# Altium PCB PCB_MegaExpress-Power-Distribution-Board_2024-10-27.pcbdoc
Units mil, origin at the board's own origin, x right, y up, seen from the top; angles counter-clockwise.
Board outline 2590 x 2205 mil, 2 copper layers (Top Layer, Bottom Layer); 6 components, 4 nets, 16 pads, 0 vias.
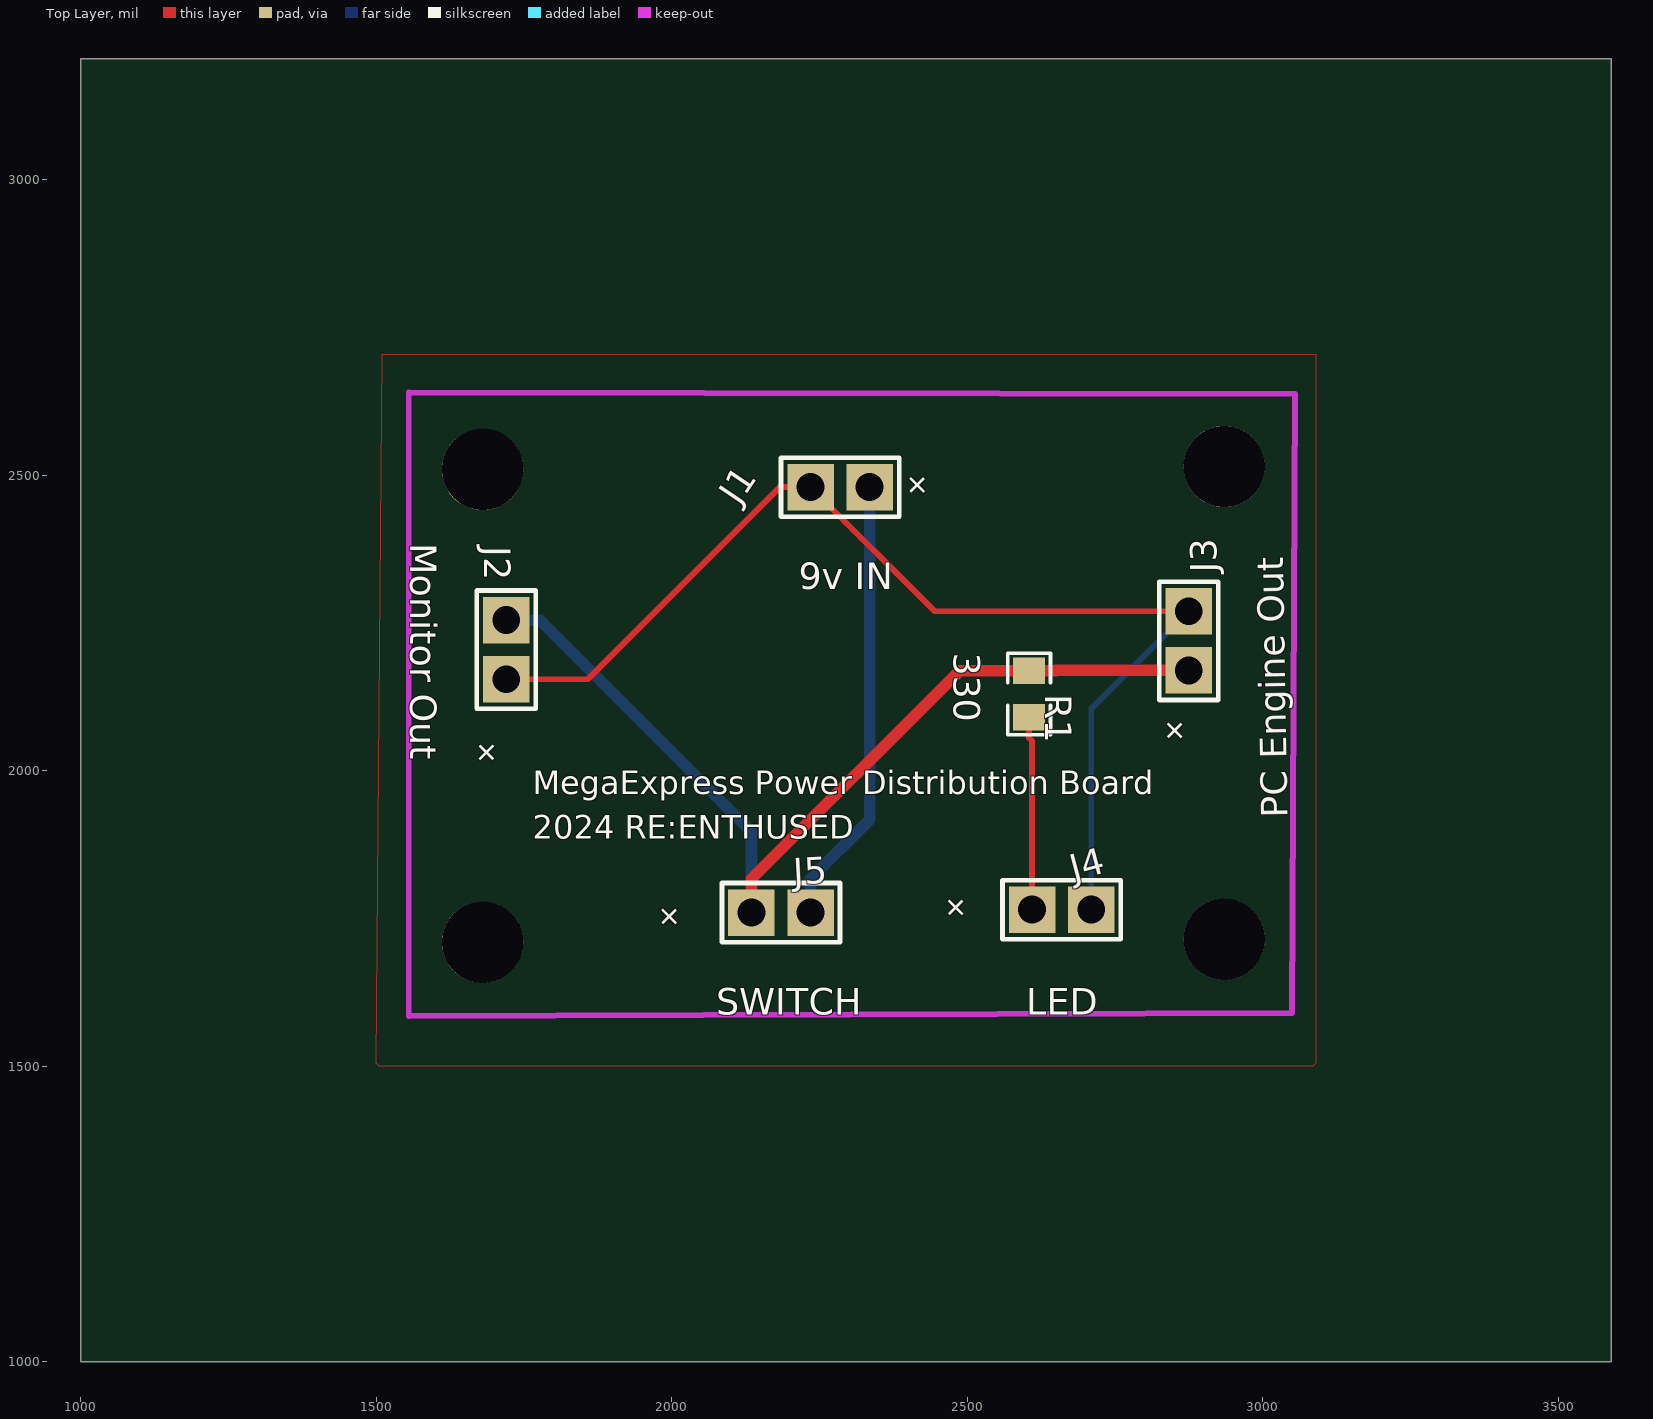
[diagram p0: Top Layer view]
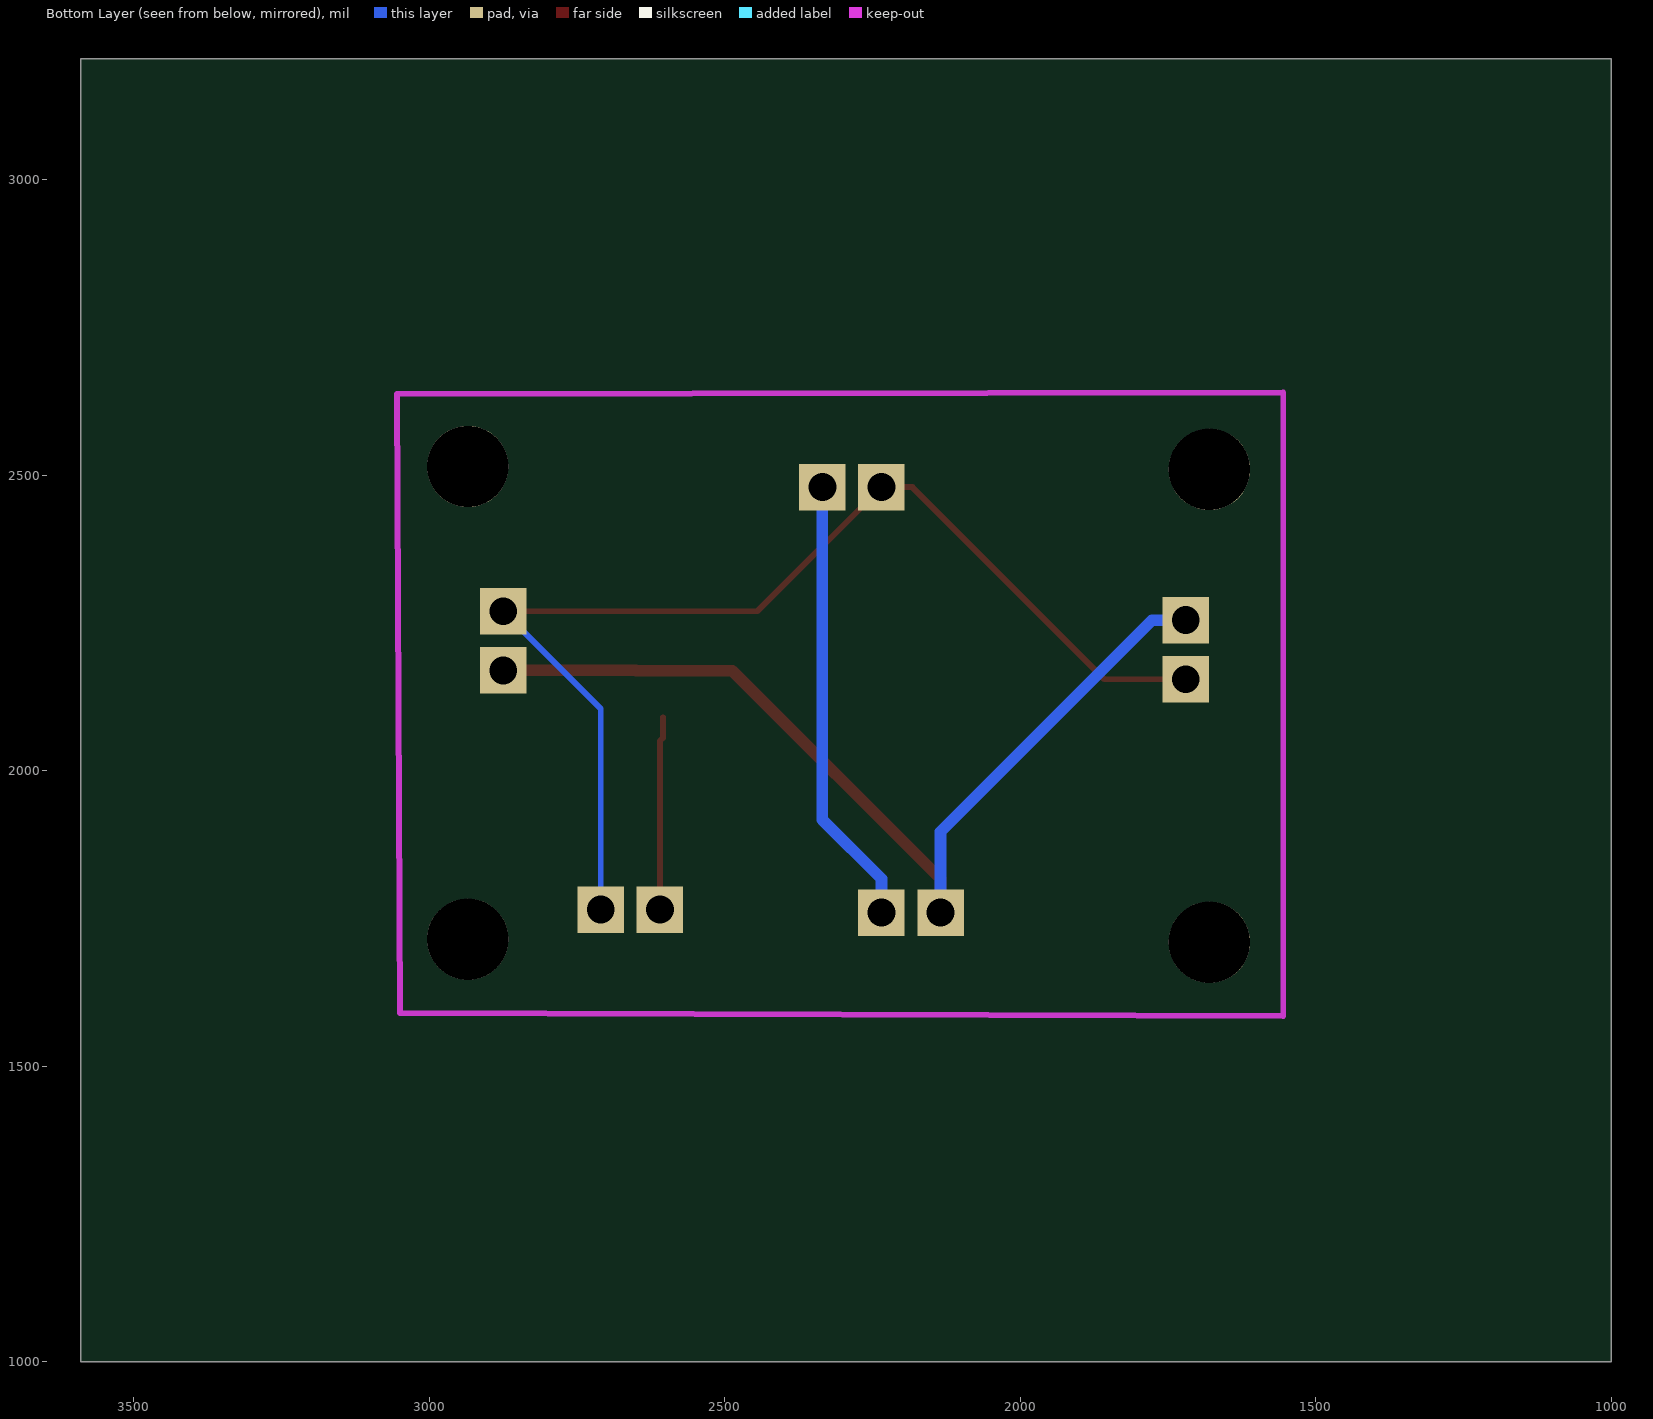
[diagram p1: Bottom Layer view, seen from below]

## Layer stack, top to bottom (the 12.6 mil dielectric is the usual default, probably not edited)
Top Layer: signal copper (thickness not stored)
Dielectric: dielectric 12.6, FR-4, Dk 4.8
Bottom Layer: signal copper (thickness not stored)

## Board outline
3590,1000 1000,1000 1000,3205 3590,3205

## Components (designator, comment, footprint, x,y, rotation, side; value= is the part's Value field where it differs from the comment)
J1 "9v IN" HDR-M-2.54_1X2 2285,2480 r180 top
J2 "Monitor Out" HDR-M-2.54_1X2 1720,2205 r270 top
J3 "PC Engine Out" HDR-M-2.54_1X2 2875,2220 r90 top
J4 "LED" HDR-M-2.54_1X2 2660,1765 r0 top
J5 "SWITCH" HDR-M-2.54_1X2 2185,1760 r0 top
R1 "330" R0805 2605,2130 r270 top

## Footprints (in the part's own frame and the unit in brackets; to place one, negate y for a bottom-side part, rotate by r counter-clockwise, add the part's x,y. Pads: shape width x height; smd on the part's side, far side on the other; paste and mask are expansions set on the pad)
HDR-M-2.54_1X2 [mm]
  rect 2x2 hole 1.2 paste+0 mask+0.051: 1(-1.27,0) 2(1.27,0)
  silkscreen extent -2.54,-1.27 2.54,1.27
R0805 [mil]
  rect 44.59x54.21 smd paste-3937.01 mask+2: 1(-39.37,0) 2(39.37,0)
  silkscreen extent -69,-36 69,36

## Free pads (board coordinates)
  round 137.8 hole 137.8 unplated paste+0: ""(1680,1710) ""(1680,2510) ""(2935,1715) ""(2935,2515)

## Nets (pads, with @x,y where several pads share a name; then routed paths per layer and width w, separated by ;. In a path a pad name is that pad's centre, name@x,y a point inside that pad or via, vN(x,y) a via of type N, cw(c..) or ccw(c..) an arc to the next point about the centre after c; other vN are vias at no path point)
9V-IN: J1.1 J5.2 | length 761.4
  Bottom Layer w19.68: J5.2 2235,1817.1 2335,1917.1 J1.1
9V-OUT: J2.1 J3.1 J5.1 R1.1 | length 1643.6
  Top Layer w19.68: J5.1 2135,1817.1 2487.27,2169.37 R1.1 2649.84,2169.37 2650.47,2170 J3.1
  Bottom Layer w19.68: J2.1 1777.1,2255 2135,1897.1 J5.1
GND: J1.2 J2.2 J3.2 J4.2 | length 1949.9
  Top Layer w10: J2.2 1857.74,2155 2182.74,2480 J1.2 2445,2270 J3.2
  Bottom Layer w10: J4.2 2710,2105 J3.2
J4_1: J4.1 R1.2 | length 327.7
  Top Layer w10: R1.2 2605,2055.44 2610,2050.44 J4.1

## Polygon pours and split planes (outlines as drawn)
GND on Top Layer (solid): 1510,2705 3090,2705 3090,1505 3085,1500 1505,1500 1500,1505

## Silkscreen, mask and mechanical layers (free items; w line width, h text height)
Top Overlay:
  text "+" at 2443.92,2478.92 h39.37 r135
  text "+" at 2878.92,2063.92 h39.37 r135
  text "+" at 1691.08,2058.92 h39.37 r225
  text "MegaExpress Power Distribution Board" at 1765,1960.32 h39.37
  text "2024 RE:ENTHUSED" at 1765,1885.32 h39.37
  text "+" at 2508.92,1763.92 h39.37 r135
  text "+" at 2023.92,1748.92 h39.37 r135
Document:
  lines w0.1: 2294.99,2102.49 2295.01,2102.51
